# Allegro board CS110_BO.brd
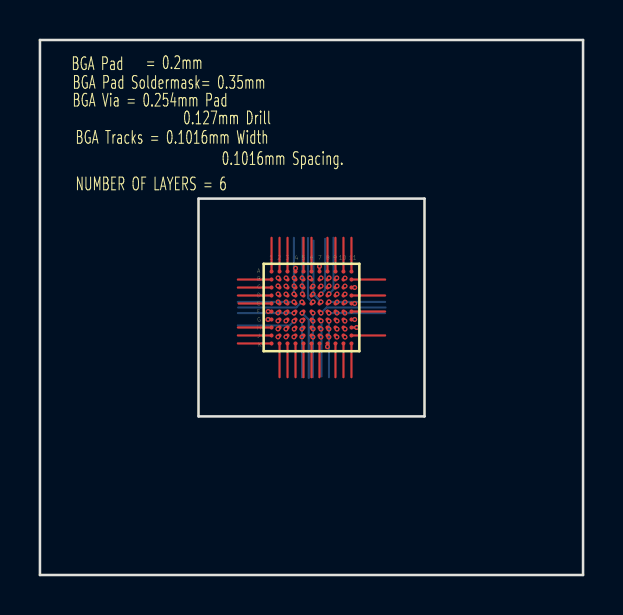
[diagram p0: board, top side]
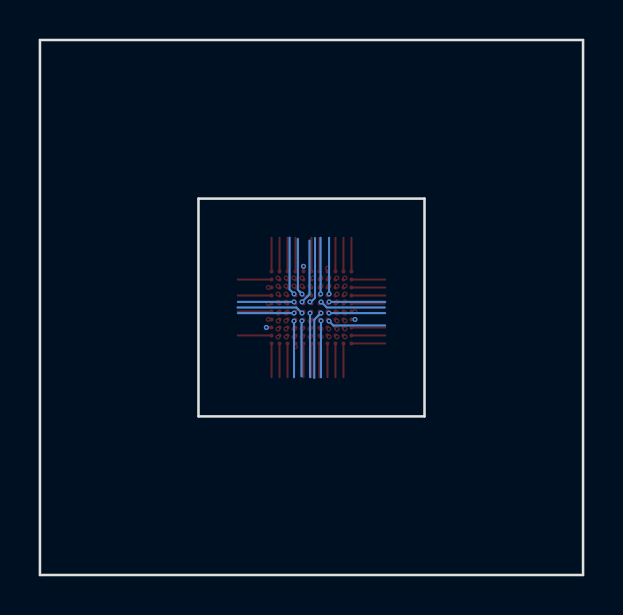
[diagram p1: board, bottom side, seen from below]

Outline 27.19 x 26.77 mm; copper layers: TOP, L2_GND, SIGNAL-1, SIGNAL2, L4_POWER, BOTTOM. Coordinates in mm from the lower left corner of the outline.
Outline path: 0,26.77 0,0 27.19,0 27.19,26.77 0,26.77 ; 7.94,18.84 7.94,7.94 19.25,7.94 19.25,18.84 7.94,18.84

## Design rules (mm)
net group BGA: nets A3 A5 A6 A8 A9 A10 A11 B1 B2 B3 B4 B5 B6 B7 B8 B9 B10 B11 C1 C2 C3 C4 C5 C6 C7 C8 C9 C10 D1 D2 D3 D4 D5 D6 D7 D8 D9 D10 D11 E1 E2 E3 E4 E5 E6 E7 E8 E9 E10 F2 F3 F4 F5 F6 F7 F8 F9 F10 F11 G2 G3 G4 G5 G6 G7 G8 G9 G10 GND H1 H2 H3 H4 H5 H6 H7 H8 H9 H10 J1 J2 J3 J4 J5 J6 J7 J8 J9 J10 J11 K1 K2 K3 K4 K5 K6 K7 K9 K10 K11 VCC VPP_2V5 VPP_FAST

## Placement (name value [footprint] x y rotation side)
U1  -  [CS110]  11.59 15.19 0 top

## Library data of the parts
U1 = CS110

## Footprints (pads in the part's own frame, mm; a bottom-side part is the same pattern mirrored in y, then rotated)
CS110
  round 0.2 smd: A1(0,0) A2(0.4,0) A3(0.8,0) A4(1.2,0) A5(1.6,0) A6(2,0) A7(2.4,0) A8(2.8,0) A9(3.2,0) A10(3.6,0) A11(4,0) B1(0,-0.4) B2(0.4,-0.4) B3(0.8,-0.4) B4(1.2,-0.4) B5(1.6,-0.4) B6(2,-0.4) B7(2.4,-0.4) B8(2.8,-0.4) B9(3.2,-0.4) B10(3.6,-0.4) B11(4,-0.4) C1(0,-0.8) C2(0.4,-0.8) C3(0.8,-0.8) C4(1.2,-0.8) C5(1.6,-0.8) C6(2,-0.8) C7(2.4,-0.8) C8(2.8,-0.8) C9(3.2,-0.8) C10(3.6,-0.8) C11(4,-0.8) D1(0,-1.2) D2(0.4,-1.2) D3(0.8,-1.2) D4(1.2,-1.2) D5(1.6,-1.2) D6(2,-1.2) D7(2.4,-1.2) D8(2.8,-1.2) D9(3.2,-1.2) D10(3.6,-1.2) D11(4,-1.2) E1(0,-1.6) E2(0.4,-1.6) E3(0.8,-1.6) E4(1.2,-1.6) E5(1.6,-1.6) E6(2,-1.6) E7(2.4,-1.6) E8(2.8,-1.6) E9(3.2,-1.6) E10(3.6,-1.6) E11(4,-1.6) F1(0,-2) F2(0.4,-2) F3(0.8,-2) F4(1.2,-2) F5(1.6,-2) F6(2,-2) F7(2.4,-2) F8(2.8,-2) F9(3.2,-2) F10(3.6,-2) F11(4,-2) G1(0,-2.4) G2(0.4,-2.4) G3(0.8,-2.4) G4(1.2,-2.4) G5(1.6,-2.4) G6(2,-2.4) G7(2.4,-2.4) G8(2.8,-2.4) G9(3.2,-2.4) G10(3.6,-2.4) G11(4,-2.4) H1(0,-2.8) H2(0.4,-2.8) H3(0.8,-2.8) H4(1.2,-2.8) H5(1.6,-2.8) H6(2,-2.8) H7(2.4,-2.8) H8(2.8,-2.8) H9(3.2,-2.8) H10(3.6,-2.8) H11(4,-2.8) J1(0,-3.2) J2(0.4,-3.2) J3(0.8,-3.2) J4(1.2,-3.2) J5(1.6,-3.2) J6(2,-3.2) J7(2.4,-3.2) J8(2.8,-3.2) J9(3.2,-3.2) J10(3.6,-3.2) J11(4,-3.2) K1(0,-3.6) K2(0.4,-3.6) K3(0.8,-3.6) K4(1.2,-3.6) K5(1.6,-3.6) K6(2,-3.6) K7(2.4,-3.6) K8(2.8,-3.6) K9(3.2,-3.6) K10(3.6,-3.6) K11(4,-3.6)

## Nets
GND: U1.A4 U1.C11 U1.E11 U1.F1 U1.G11 U1.K8
VCC: U1.A7 U1.G1 U1.H11
A3: U1.A3
A5: U1.A5
A6: U1.A6
A8: U1.A8
A9: U1.A9
A10: U1.A10
A11: U1.A11
B1: U1.B1
B2: U1.B2
B3: U1.B3
B4: U1.B4
B5: U1.B5
B6: U1.B6
B7: U1.B7
B8: U1.B8
B9: U1.B9
B10: U1.B10
B11: U1.B11
C1: U1.C1
C2: U1.C2
C3: U1.C3
C4: U1.C4
C5: U1.C5
C6: U1.C6
C7: U1.C7
C8: U1.C8
C9: U1.C9
C10: U1.C10
D1: U1.D1
D2: U1.D2
D3: U1.D3
D4: U1.D4
D5: U1.D5
D6: U1.D6
D7: U1.D7
D8: U1.D8
D9: U1.D9
D10: U1.D10
D11: U1.D11
E1: U1.E1
E2: U1.E2
E3: U1.E3
E4: U1.E4
E5: U1.E5
E6: U1.E6
E7: U1.E7
E8: U1.E8
E9: U1.E9
E10: U1.E10
F2: U1.F2
F3: U1.F3
F4: U1.F4
F5: U1.F5
F6: U1.F6
F7: U1.F7
F8: U1.F8
F9: U1.F9
F10: U1.F10
F11: U1.F11
G2: U1.G2
G3: U1.G3
G4: U1.G4
G5: U1.G5
G6: U1.G6
G7: U1.G7
G8: U1.G8
G9: U1.G9
G10: U1.G10
H1: U1.H1
H2: U1.H2
H3: U1.H3
H4: U1.H4
H5: U1.H5
H6: U1.H6
H7: U1.H7
H8: U1.H8
H9: U1.H9
H10: U1.H10
J1: U1.J1
J2: U1.J2
J3: U1.J3
J4: U1.J4
J5: U1.J5
J6: U1.J6
J7: U1.J7
J8: U1.J8
J9: U1.J9
J10: U1.J10
J11: U1.J11
K1: U1.K1
K2: U1.K2
K3: U1.K3
K4: U1.K4
K5: U1.K5
K6: U1.K6
K7: U1.K7
K9: U1.K9
K10: U1.K10
K11: U1.K11
VPP_2V5: U1.A1
VPP_FAST: U1.A2

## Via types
v1: diameter 0.254, hole 0.127, TOP to SIGNAL-1, 31 vias
v2: diameter 0.254, hole 0.127, TOP to SIGNAL2, 23 vias
v3: diameter 0.254, hole 0.127, TOP to BOTTOM, 21 vias
v4: diameter 0.254, hole 0.127, TOP to L2_GND, 6 vias

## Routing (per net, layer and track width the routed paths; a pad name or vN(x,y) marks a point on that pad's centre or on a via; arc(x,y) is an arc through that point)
GND: length 1
  TOP w0.102: U1.K8 v4(14.39,11.42) ; v4(12.79,15.35) U1.A4 ; v4(15.76,14.39) U1.C11 ; 15.59,13.59 U1.E11 15.59,13.59 ; 15.59,13.59 v4(15.76,13.59) ; v4(15.76,12.79) U1.G11 ; v4(11.42,13.19) U1.F1
VCC: length 0.7
  TOP w0.102: v3(15.85,12.39) 15.8,12.39 15.75,12.39 U1.H11 ; U1.G1 v3(11.42,12.79) ; v3(13.99,15.45) U1.A7
A3: length 1.7
  TOP w0.102: U1.A3 12.39,16.87
A5: length 1.7
  TOP w0.102: U1.A5 13.19,16.87
A6: length 1.7
  TOP w0.102: U1.A6 13.59,16.87
A8: length 1.7
  TOP w0.102: U1.A8 14.39,16.87
A9: length 1.7
  TOP w0.102: U1.A9 14.79,16.87
A10: length 1.7
  TOP w0.102: U1.A10 15.19,16.87
A11: length 1.7
  TOP w0.102: U1.A11 15.59,16.87
B1: length 1.7
  TOP w0.102: U1.B1 9.91,14.79
B2: length 2.1
  TOP w0.102: v1(11.92,14.86) 11.99,14.79 U1.B2
  SIGNAL-1 w0.102: v1(11.92,14.86) 11.92,16.86
B3: length 2.1
  TOP w0.102: U1.B3 12.39,14.79 v1(12.32,14.86)
  SIGNAL-1 w0.102: v1(12.32,14.86) 12.32,16.86
B4: length 2.1
  TOP w0.102: U1.B4 12.79,14.8 v1(12.73,14.86)
  SIGNAL-1 w0.102: v1(12.73,14.86) 12.73,16.86
B5: length 2.1
  TOP w0.102: U1.B5 13.19,14.79 v1(13.12,14.86)
  SIGNAL-1 w0.102: v1(13.12,14.86) 13.12,16.86
B6: length 2.1
  TOP w0.102: v1(13.51,14.87) 13.59,14.79 U1.B6
  SIGNAL-1 w0.102: v1(13.51,14.87) 13.43,14.95 13.43,16.87
B7: length 2.2
  TOP w0.102: v1(14.08,14.86) 14,14.79 U1.B7
  SIGNAL-1 w0.102: 14.27,16.86 14.27,15.56 14.27,15.56 14.27,15.33 14.27,15.33 14.27,15.06 14.08,14.86 v1(14.08,14.86)
B8: length 2.1
  TOP w0.102: U1.B8 14.39,14.79 v1(14.48,14.87)
  SIGNAL-1 w0.102: v1(14.48,14.87) 14.55,14.94 14.55,16.87
B9: length 2.1
  TOP w0.102: U1.B9 14.79,14.8 v1(14.86,14.86)
  SIGNAL-1 w0.102: v1(14.86,14.86) 14.86,16.86
B10: length 2.1
  TOP w0.102: U1.B10 15.2,14.79 v1(15.27,14.86)
  SIGNAL-1 w0.102: v1(15.27,14.86) 17.27,14.86
B11: length 1.7
  TOP w0.102: U1.B11 17.28,14.79
C1: length 1.7
  TOP w0.102: U1.C1 9.91,14.39
C2: length 2.1
  TOP w0.102: U1.C2 11.99,14.39 v1(11.92,14.47)
  SIGNAL-1 w0.102: v1(11.92,14.47) 9.92,14.47
C3: length 2.5
  TOP w0.102: v2(12.31,14.46) 12.39,14.39 U1.C3
  SIGNAL2 w0.102: v2(12.31,14.46) 12.31,16.86
C4: length 2.5
  TOP w0.102: U1.C4 12.79,14.39 v2(12.72,14.47)
  SIGNAL2 w0.102: v2(12.72,14.47) 12.72,16.87
C5: length 2.5
  TOP w0.102: U1.C5 13.19,14.39 v2(13.12,14.47)
  SIGNAL2 w0.102: 13.12,14.46 v2(13.12,14.47) 13.12,16.87
C6: length 2.6
  TOP w0.102: v1(13.67,14.46) 13.6,14.39 U1.C6
  SIGNAL-1 w0.102: 13.7,16.87 13.7,15.08 13.79,14.98 13.79,14.58 v1(13.67,14.46)
C7: length 2.6
  TOP w0.102: v2(14.07,14.46) 14,14.39 U1.C7
  SIGNAL2 w0.102: v2(14.07,14.46) 14.31,14.69 14.31,16.87
C8: length 2.6
  TOP w0.102: v2(14.47,14.46) 14.4,14.39 U1.C8
  SIGNAL2 w0.102: v2(14.47,14.46) 14.59,14.58 14.59,16.87
C9: length 2.5
  TOP w0.102: v2(14.87,14.46) 14.8,14.39 U1.C9
  SIGNAL2 w0.102: v2(14.87,14.46) 14.87,16.87
C10: length 2.1
  TOP w0.102: U1.C10 15.2,14.39 v1(15.27,14.46)
  SIGNAL-1 w0.102: v1(15.27,14.46) 17.27,14.46
D1: length 1.7
  TOP w0.102: U1.D1 11.59,13.99 9.91,13.99
D2: length 2.1
  TOP w0.102: v1(11.92,14.06) 11.99,13.99 U1.D2
  SIGNAL-1 w0.102: v1(11.92,14.06) 9.92,14.06
D3: length 2.5
  TOP w0.102: v2(12.32,14.05) 12.38,13.99 U1.D3
  SIGNAL2 w0.102: v2(12.32,14.05) 9.91,14.05
D4: length 2.9
  TOP w0.102: U1.D4 12.79,13.99 v3(12.71,14.06)
  BOTTOM w0.102: v3(12.71,14.06) 12.71,16.87
D5: length 2.9
  TOP w0.102: U1.D5 13.19,14.01 v3(13.14,14.06)
  BOTTOM w0.102: v3(13.14,14.06) 13.14,16.87
D6: length 3
  TOP w0.102: v2(13.67,14.06) 13.6,13.99 U1.D6
  SIGNAL2 w0.102: v2(13.67,14.06) 13.64,14.06 13.43,14.27 13.43,16.85
D7: length 5.9
  TOP w0.102: v3(14.07,14.06) 14,13.99 U1.D7
  SIGNAL2 w0.102: 13.71,16.87 13.71,14.42 v3(14.07,14.06)
  BOTTOM w0.102: 14.28,16.82 14.28,14.27 14.19,14.18 14.07,14.07 v3(14.07,14.06)
D8: length 3
  TOP w0.102: v3(14.47,14.07) 14.39,13.99 U1.D8
  BOTTOM w0.102: v3(14.47,14.07) 14.69,14.29 14.69,16.88
D9: length 2.5
  TOP w0.102: U1.D9 14.8,13.99 v2(14.87,14.06)
  SIGNAL2 w0.102: v2(14.87,14.06) 17.28,14.06
D10: length 2.1
  TOP w0.102: v1(15.27,14.06) 15.2,13.99 U1.D10
  SIGNAL-1 w0.102: v1(15.27,14.06) 17.27,14.06
D11: length 1.7
  TOP w0.102: U1.D11 15.59,13.99 17.28,13.99
E1: length 1.7
  TOP w0.102: U1.E1 11.59,13.59 9.94,13.59
E2: length 2.1
  TOP w0.102: v1(11.92,13.67) 11.99,13.59 U1.E2
  SIGNAL-1 w0.102: v1(11.92,13.67) 9.92,13.67
E3: length 2.5
  TOP w0.102: U1.E3 12.39,13.59 v2(12.32,13.67)
  SIGNAL2 w0.102: v2(12.32,13.67) 9.91,13.67
E4: length 2.9
  TOP w0.102: U1.E4 12.79,13.59 v3(12.71,13.67)
  BOTTOM w0.102: v3(12.71,13.67) 9.9,13.67
E5: length 3.4
  TOP w0.102: U1.E5 13.19,13.59 v3(13.11,13.66)
  BOTTOM w0.102: v3(13.11,13.66) 13.1,13.66 12.83,13.39 9.93,13.39
E6: length 3.4
  TOP w0.102: v3(13.67,13.67) 13.6,13.59 U1.E6
  BOTTOM w0.102: v3(13.67,13.67) 13.62,13.67 13.42,13.87 13.42,16.86
E7: length 3.3
  TOP w0.102: v3(14.07,13.67) 13.99,13.59 U1.E7
  BOTTOM w0.102: 13.69,16.73 13.69,14.05 13.79,13.95 13.79,13.94 14.07,13.67 v3(14.07,13.67)
E8: length 2.9
  TOP w0.102: v3(14.47,13.67) 14.39,13.59 U1.E8
  BOTTOM w0.102: v3(14.47,13.67) 17.28,13.67
E9: length 2.5
  TOP w0.102: v2(14.87,13.66) 14.8,13.59 U1.E9
  SIGNAL2 w0.102: v2(14.87,13.66) 17.28,13.66
E10: length 2.1
  TOP w0.102: v1(15.27,13.66) 15.2,13.59 U1.E10
  SIGNAL-1 w0.102: v1(15.27,13.66) 17.27,13.66
F2: length 2.1
  TOP w0.102: U1.F2 11.99,13.19 v1(11.92,13.12)
  SIGNAL-1 w0.102: v1(11.92,13.12) 9.92,13.12
F3: length 2.5
  TOP w0.102: U1.F3 12.39,13.19 v2(12.31,13.11)
  SIGNAL2 w0.102: v2(12.31,13.11) 9.91,13.11
F4: length 2.9
  TOP w0.102: U1.F4 12.79,13.18 v3(12.72,13.11)
  BOTTOM w0.102: v3(12.72,13.11) 9.91,13.11
F5: length 3.5
  TOP w0.102: v3(13.12,13.11) 13.19,13.18 U1.F5
  BOTTOM w0.102: 13.46,9.87 13.46,12.78 13.23,13 13.22,13 v3(13.12,13.11)
F6: length 3.3
  TOP w0.102: U1.F6 13.59,13.18 v3(13.67,13.11)
  BOTTOM w0.102: v3(13.67,13.11) 13.67,9.9
F7: length 3.5
  TOP w0.102: v3(14.07,13.11) 13.99,13.18 U1.F7
  BOTTOM w0.102: v3(14.07,13.11) 14.07,13.11 14.35,13.39 17.3,13.39
F8: length 2.9
  TOP w0.102: U1.F8 14.39,13.18 v3(14.47,13.11)
  BOTTOM w0.102: v3(14.47,13.11) 17.28,13.11
F9: length 2.5
  TOP w0.102: U1.F9 14.8,13.19 v2(14.87,13.11)
  SIGNAL2 w0.102: v2(14.87,13.11) 17.28,13.11
F10: length 2.1
  TOP w0.102: U1.F10 15.19,13.18 v1(15.26,13.11)
  SIGNAL-1 w0.102: v1(15.26,13.11) 17.26,13.11
F11: length 1.7
  TOP w0.102: U1.F11 17.28,13.19
G2: length 2.2
  TOP w0.102: U1.G2 11.99,12.79 v1(11.92,12.72)
  SIGNAL-1 w0.102: v1(11.92,12.72) 11.67,12.47 9.92,12.47
G3: length 2.6
  TOP w0.102: U1.G3 12.39,12.79 v2(12.31,12.71)
  SIGNAL2 w0.102: v2(12.31,12.71) 12.11,12.51 9.91,12.51
G4: length 3
  TOP w0.102: U1.G4 12.79,12.78 v3(12.72,12.71)
  BOTTOM w0.102: 9.91,12.49 12.5,12.49 v3(12.72,12.71)
G5: length 2.9
  TOP w0.102: U1.G5 13.18,12.79 v3(13.12,12.72)
  BOTTOM w0.102: 13.12,9.89 13.12,12.57 13.12,12.57 13.12,12.72 v3(13.12,12.72)
G6: length 3
  TOP w0.102: U1.G6 13.59,12.78 v2(13.67,12.71)
  SIGNAL2 w0.102: v2(13.67,12.71) 13.57,12.6 13.56,12.6 13.4,12.44 13.4,12.43 13.39,12.43 13.39,12.2 13.42,12.17 13.42,9.91
G7: length 2.9
  TOP w0.102: U1.G7 14.06,12.72 v3(14.07,12.72)
  BOTTOM w0.102: v3(14.07,12.72) 14.09,12.7 14.09,9.94
G8: length 2.9
  TOP w0.102: U1.G8 14.39,12.78 v3(14.47,12.71)
  BOTTOM w0.102: v3(14.47,12.71) 14.47,9.89
G9: length 2.5
  TOP w0.102: v2(14.87,12.71) 14.8,12.79 U1.G9
  SIGNAL2 w0.102: v2(14.87,12.71) 17.28,12.71
G10: length 2.1
  TOP w0.102: U1.G10 15.19,12.78 v1(15.26,12.71)
  SIGNAL-1 w0.102: v1(15.26,12.71) 17.26,12.71
H1: length 1.7
  TOP w0.102: U1.H1 9.91,12.39
H2: length 2.1
  TOP w0.102: v1(11.92,12.31) 11.99,12.39 U1.H2
  SIGNAL-1 w0.102: 9.92,12.27 11.87,12.27 v1(11.92,12.31)
H3: length 2.5
  TOP w0.102: v2(12.31,12.31) 12.39,12.39 U1.H3
  SIGNAL2 w0.102: v2(12.31,12.31) 12.31,12.3 9.91,12.3
H4: length 2.5
  TOP w0.102: U1.H4 12.79,12.37 v2(12.73,12.31)
  SIGNAL2 w0.102: v2(12.73,12.31) 12.73,9.9
H5: length 2.5
  TOP w0.102: U1.H5 13.19,12.39 v2(13.11,12.31)
  SIGNAL2 w0.102: v2(13.11,12.31) 13.11,9.91
H6: length 2.3
  TOP w0.102: U1.H6 13.67,12.31 v2(13.67,12.31)
  SIGNAL2 w0.102: v2(13.67,12.31) 13.67,10.14
H7: length 2.5
  TOP w0.102: v2(14.07,12.31) 14.07,12.31 U1.H7
  SIGNAL2 w0.102: v2(14.07,12.31) 14.07,9.9
H8: length 2.5
  TOP w0.102: v2(14.46,12.31) 14.46,12.32 U1.H8
  SIGNAL2 w0.102: v2(14.46,12.31) 14.46,9.9
H9: length 2.5
  TOP w0.102: U1.H9 14.87,12.31 v2(14.87,12.31)
  SIGNAL2 w0.102: v2(14.87,12.31) 14.87,9.9
H10: length 2.2
  TOP w0.102: v1(15.27,12.31) U1.H10
  SIGNAL-1 w0.102: 17.27,12.08 15.5,12.08 v1(15.27,12.3)
J1: length 1.7
  TOP w0.102: 9.91,11.99 11.59,11.99 U1.J1
J2: length 2.1
  TOP w0.102: U1.J2 11.99,11.99 v1(11.92,11.92)
  SIGNAL-1 w0.102: v1(11.92,11.92) 11.92,9.92
J3: length 2.1
  TOP w0.102: U1.J3 12.39,11.99 v1(12.32,11.92)
  SIGNAL-1 w0.102: v1(12.32,11.92) 12.32,9.92
J4: length 2.1
  TOP w0.102: U1.J4 12.79,11.99 v1(12.72,11.92)
  SIGNAL-1 w0.102: v1(12.72,11.92) 12.72,9.92
J5: length 2.1
  TOP w0.102: v1(13.12,11.92) 13.19,11.99 U1.J5
  SIGNAL-1 w0.102: v1(13.12,11.92) 13.12,9.92
J6: length 2.1
  TOP w0.102: U1.J6 13.59,11.98 v1(13.66,11.91)
  SIGNAL-1 w0.102: v1(13.66,11.91) 13.66,9.91
J7: length 2.1
  TOP w0.102: v1(14.06,11.91) 13.99,11.98 U1.J7
  SIGNAL-1 w0.102: v1(14.06,11.91) 14.06,9.91
J8: length 2.1
  TOP w0.102: v1(14.47,11.91) 14.39,11.98 U1.J8
  SIGNAL-1 w0.102: v1(14.47,11.91) 14.47,9.91
J9: length 2.1
  TOP w0.102: U1.J9 14.79,11.98 v1(14.86,11.91)
  SIGNAL-1 w0.102: v1(14.86,11.91) 14.86,9.91
J10: length 2.1
  TOP w0.102: v1(15.27,11.91) 15.27,11.91 U1.J10
  SIGNAL-1 w0.102: v1(15.27,11.91) 15.27,9.91
J11: length 1.7
  TOP w0.102: U1.J11 15.59,11.99 17.28,11.99
K1: length 1.7
  TOP w0.102: 9.91,11.59 11.59,11.59 U1.K1
K2: length 1.7
  TOP w0.102: U1.K2 11.99,11.59 11.99,9.9
K3: length 1.7
  TOP w0.102: U1.K3 12.39,9.9
K4: length 1.7
  TOP w0.102: U1.K4 12.79,11.59 12.79,9.9
K5: length 1.7
  TOP w0.102: U1.K5 13.19,11.59 13.19,9.9
K6: length 1.7
  TOP w0.102: 13.59,9.9 13.59,11.59 U1.K6
K7: length 1.7
  TOP w0.102: 13.99,9.9 13.99,11.59 U1.K7
K9: length 1.7
  TOP w0.102: U1.K9 14.79,11.59 14.79,9.9
K10: length 1.7
  TOP w0.102: 15.19,9.9 15.19,11.59 U1.K10
K11: length 1.7
  TOP w0.102: U1.K11 15.59,11.59 15.59,9.9
VPP_2V5: length 1.7
  TOP w0.102: U1.A1 11.59,16.87
VPP_FAST: length 1.7
  TOP w0.102: U1.A2 11.99,16.87

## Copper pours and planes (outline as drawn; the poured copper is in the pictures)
GND on L2_GND (solid shape): outline of 135 points within 11.21,11.18 16.02,15.58
VCC on L4_POWER: 11.16,15.59 11.16,11.17 16.03,11.17 16.03,15.59
(no net) on L2_GND: 11.21,15.58 11.21,11.18 16.02,11.18 16.02,15.58

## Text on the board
Ref Des/Silkscreen Top: BGA Pad | BGA Via = 0.254mm Pad | BGA Pad Soldermask= 0.35mm | BGA Tracks = 0.1016mm Width | NUMBER OF LAYERS = 6 | = 0.2mm | 0.127mm Drill | 0.1016mm Spacing.
NCLEGEND-1-2: FIGURE | SIZE | 5.0 | DRILL CHART: TOP to L2_GND | ALL UNITS ARE IN MILS | PLATED | QTY | 6
NCLEGEND-1-3: FIGURE | SIZE | 5.0 | DRILL CHART: TOP to SIGNAL-1 | ALL UNITS ARE IN MILS | PLATED | QTY | 31
User.5: FIGURE | SIZE | 5.0 | DRILL CHART: TOP to BOTTOM | ALL UNITS ARE IN MILS | PLATED | QTY | 21
User.6: FIGURE | SIZE | 5.0 | DRILL CHART: TOP to SIGNAL2 | ALL UNITS ARE IN MILS | PLATED | QTY | 23
